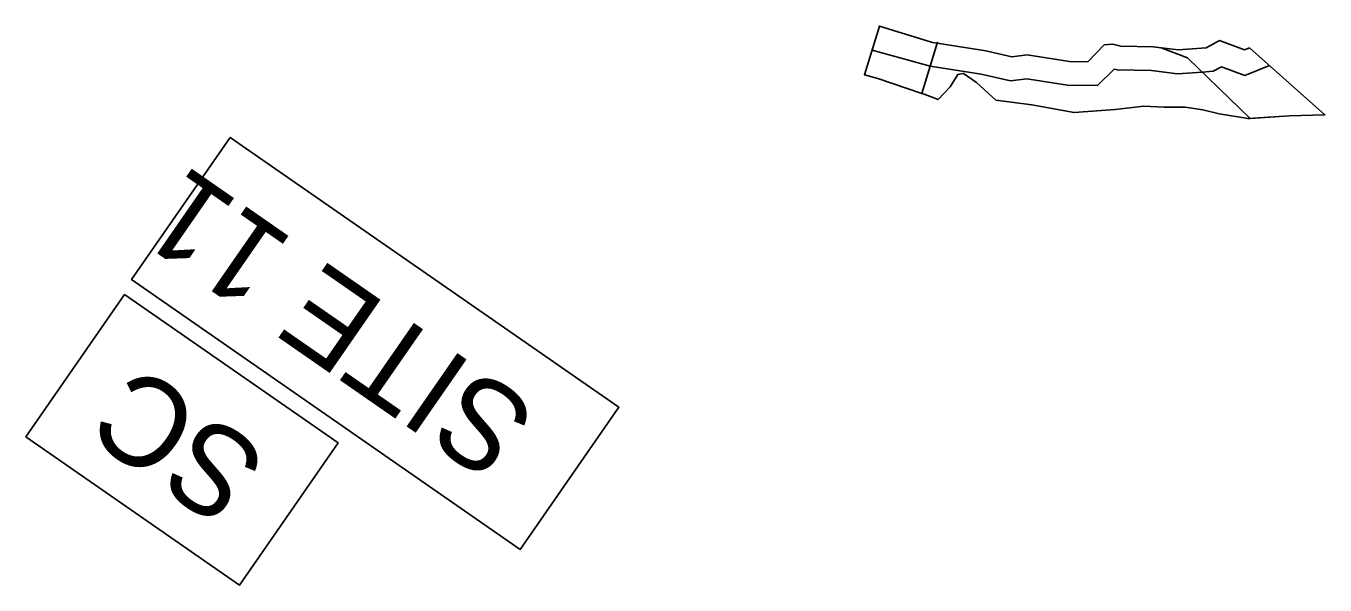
# Model space of a CAD drawing. Extents: x 474218 to 481634, y 484357 to 504997.
# Drawn here: x 478782.8 to 479001.4, y 493915.3 to 494009.3 of the extents above; entities that cross this region are included whole.
import ezdxf

# ---------------------------------------------------------------- set-up
doc = ezdxf.new("R2010")
doc.units = 0
for name, color, linetype in [('Exist Hydro Jurisdictional Stream or Body of Water', 7, 'Continuous'), ('Old_Level_29', 7, 'Continuous'), ('Prop Earthen Structure Impacts In Surface Waters Hatching CELL', 7, 'Continuous'), ('Prop Grid Mask', 7, 'Continuous'), ('Scratch_Level_4', 7, 'Continuous'), ('Temp Earthen Structure Impacts In Surface Waters Hatching CELL', 7, 'Continuous')]:
    doc.layers.add(name, color=color, linetype=linetype)

msp = doc.modelspace()

# ---------------------------------------------------------------- linework, layer by layer
at = {"layer": 'Exist Hydro Jurisdictional Stream or Body of Water'}
msp.add_lwpolyline([(478818.77, 493915.27), (478782.84, 493940.2), (478799.42, 493964.09), (478835.35, 493939.17)], close=True, dxfattribs=at)
at = {"layer": 'Old_Level_29'}
msp.add_lwpolyline([(478865.99, 493921.27), (478800.62, 493966.62), (478817.2, 493990.52), (478882.57, 493945.17)], close=True, dxfattribs=at)
at = {"layer": 'Prop Earthen Structure Impacts In Surface Waters Hatching CELL'}
for p, q in [((478936.17, 494006.53), (478936.17, 494006.53)), ((478936.17, 494006.53), (478936.17, 494006.53)), ((478936.17, 494006.53), (478936.17, 494006.53)), ((479001.35, 493994.34), (478988.66, 494005.58))]:
    msp.add_line(p, q, dxfattribs=at)
for points in [[(478936.17, 494006.53), (478936.17, 494006.53), (478936.17, 494006.53), (478936.17, 494006.53), (478936.17, 494006.53), (478936.17, 494006.53), (478936.17, 494006.53), (478933.53, 493997.91), (478933.9, 493997.78), (478936.3, 493996.9), (478938.29, 493999.05), (478939.57, 494001.08), (478940.52, 494001.28), (478942.71, 493999.74), (478945.99, 493996.79), (478952.04, 493996), (478959.15, 493994.71), (478966.08, 493995.22), (478970.88, 493995.77), (478974.29, 493995.62), (478977.82, 493995.64), (478980.78, 493995.17), (478983.54, 493994.52), (478988.41, 493993.7), (478995.38, 493994.16), (479001.35, 493994.34)], [(478988.66, 494005.58), (478987.8, 494005.24), (478983.59, 494006.81), (478981.37, 494005.58), (478976.65, 494005.24), (478972.46, 494005.78), (478967.01, 494005.86), (478965.68, 494006.23), (478964.23, 494006.09), (478961.45, 494003.26), (478958.39, 494003.3), (478951.24, 494004.44), (478948.65, 494004.1), (478944.3, 494005.08), (478936.13, 494006.37), (478936.13, 494006.37), (478936.13, 494006.37), (478936.13, 494006.37), (478936.13, 494006.37), (478936.13, 494006.37), (478936.13, 494006.37), (478936.13, 494006.37), (478936.17, 494006.53)]]:
    msp.add_lwpolyline(points, dxfattribs=at)
at = {"layer": 'Prop Grid Mask'}
for points in [[(478882.57, 493945.17), (478817.2, 493990.52), (478800.62, 493966.62), (478865.99, 493921.27)], [(478835.35, 493939.17), (478799.42, 493964.09), (478782.84, 493940.2), (478818.77, 493915.27)]]:
    msp.add_lwpolyline(points, close=True, dxfattribs=at)
at = {"layer": 'Scratch_Level_4'}
msp.add_line((478934.94, 494002.51), (478925.17, 494005.2), dxfattribs=at)
for points in [[(478936.13, 494006.37), (478933.53, 493997.91), (478933.9, 493997.78), (478936.3, 493996.9), (478938.29, 493999.05), (478939.57, 494001.08), (478940.52, 494001.28), (478942.71, 493999.74), (478945.99, 493996.79), (478952.04, 493996), (478959.15, 493994.71), (478966.08, 493995.22), (478970.88, 493995.77), (478974.29, 493995.62), (478977.82, 493995.64), (478980.78, 493995.17), (478983.54, 493994.52), (478988.41, 493993.7), (478988.78, 493993.73)], [(478973.81, 494005.6), (478972.46, 494005.78), (478967.01, 494005.86), (478965.68, 494006.23), (478964.23, 494006.09), (478961.45, 494003.26), (478958.39, 494003.3), (478951.24, 494004.44), (478948.65, 494004.1), (478944.3, 494005.08), (478936.13, 494006.37), (478936.13, 494006.37)], [(478988.78, 493993.73), (478978.24, 494003.91), (478973.81, 494005.6)], [(478980.72, 494001.52), (478976.54, 494001.22), (478972.17, 494001.78), (478966.44, 494001.87), (478965.86, 494002.03), (478963.1, 493999.24), (478958.05, 493999.3), (478951.19, 494000.4), (478948.46, 494000.03), (478943.54, 494001.15), (478934.94, 494002.51)], [(478992.01, 494002.62), (478987.86, 494000.96), (478983.92, 494002.42), (478982.54, 494001.65), (478980.72, 494001.52)]]:
    msp.add_lwpolyline(points, dxfattribs=at)
msp.add_lwpolyline([(478995.38, 493994.16), (479001.35, 493994.34), (478988.66, 494005.58), (478987.8, 494005.24), (478983.59, 494006.81), (478981.37, 494005.58), (478976.65, 494005.24), (478973.81, 494005.6), (478978.24, 494003.91), (478988.78, 493993.73)], close=True, dxfattribs=at)
at = {"layer": 'Temp Earthen Structure Impacts In Surface Waters Hatching CELL'}
msp.add_lwpolyline([(478936.13, 494006.37), (478935.33, 494006.49), (478926.39, 494009.26), (478926.39, 494009.26), (478926.39, 494009.26), (478926.39, 494009.26), (478923.88, 494001.07), (478923.88, 494001.07), (478923.88, 494001.07), (478923.88, 494001.07), (478926.11, 494000.46), (478933.53, 493997.91), (478936.13, 494006.37)], dxfattribs=at)

# ---------------------------------------------------------------- texts
at = {"layer": 'Exist Hydro Jurisdictional Stream or Body of Water'}
msp.add_text('SC', height=15, rotation=145.252, dxfattribs=at).set_placement((478824.17, 493936.87))
at = {"layer": 'Old_Level_29'}
msp.add_text('SITE 11', height=15, rotation=145.252, dxfattribs=at).set_placement((478869.46, 493944.52))

doc.saveas('drawing.dxf')
